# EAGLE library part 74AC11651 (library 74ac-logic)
Octal BUS TRANSCEIVER/REGISTER, 3-state
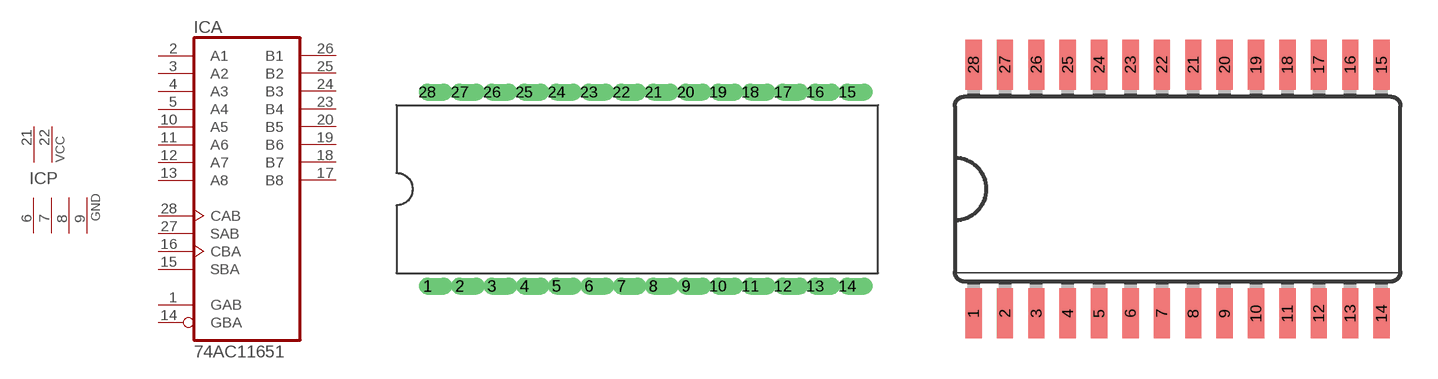
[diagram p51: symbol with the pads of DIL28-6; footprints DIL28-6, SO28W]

Designator prefix IC; gates A=7411651 P=2PWR4GND

## 74AC11651  [DIL28-6]
1  A:GAB  in
2  A:A1
3  A:A2
4  A:A3
5  A:A4
6  P:GND  pwr
7  P:GND  pwr
8  P:GND  pwr
9  P:GND  pwr
10  A:A5
11  A:A6
12  A:A7
13  A:A8
14  A:GBA  in
15  A:SBA  in
16  A:CBA  in
17  A:B8
18  A:B7
19  A:B6
20  A:B5
21  P:VCC  pwr
22  P:VCC  pwr
23  A:B4
24  A:B3
25  A:B2
26  A:B1
27  A:SAB  in
28  A:CAB  in

## 74AC11651D  [SO28W]
Pads as for DIL28-6

## Footprint DIL28-6 (pad centres in mm)
Dual In Line 0.6 inch
drill 0.813 offset: 1 -16.51,-7.62; 2 -13.97,-7.62; 3 -11.43,-7.62; 4 -8.89,-7.62; 5 -6.35,-7.62; 6 -3.81,-7.62; 7 -1.27,-7.62; 8 1.27,-7.62; 9 3.81,-7.62; 10 6.35,-7.62; 11 8.89,-7.62; 12 11.43,-7.62; 13 13.97,-7.62; 14 16.51,-7.62; 15 16.51,7.62; 16 13.97,7.62; 17 11.43,7.62; 18 8.89,7.62; 19 6.35,7.62; 20 3.81,7.62; 21 1.27,7.62; 22 -1.27,7.62; 23 -3.81,7.62; 24 -6.35,7.62; 25 -8.89,7.62; 26 -11.43,7.62; 27 -13.97,7.62; 28 -16.51,7.62

## Footprint SO28W (pad centres in mm)
Wide Small Outline package 300 mil
smd 0.66 x 2.032: 1 -8.255,-5.029; 2 -6.985,-5.029; 3 -5.715,-5.029; 4 -4.445,-5.029; 5 -3.175,-5.029; 6 -1.905,-5.029; 7 -0.635,-5.029; 8 0.635,-5.029; 9 1.905,-5.029; 10 3.175,-5.029; 11 4.445,-5.029; 12 5.715,-5.029; 13 6.985,-5.029; 14 8.255,-5.029; 15 8.255,5.029; 16 6.985,5.029; 17 5.715,5.029; 18 4.445,5.029; 19 3.175,5.029; 20 1.905,5.029; 21 0.635,5.029; 22 -0.635,5.029; 23 -1.905,5.029; 24 -3.175,5.029; 25 -4.445,5.029; 26 -5.715,5.029; 27 -6.985,5.029; 28 -8.255,5.029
